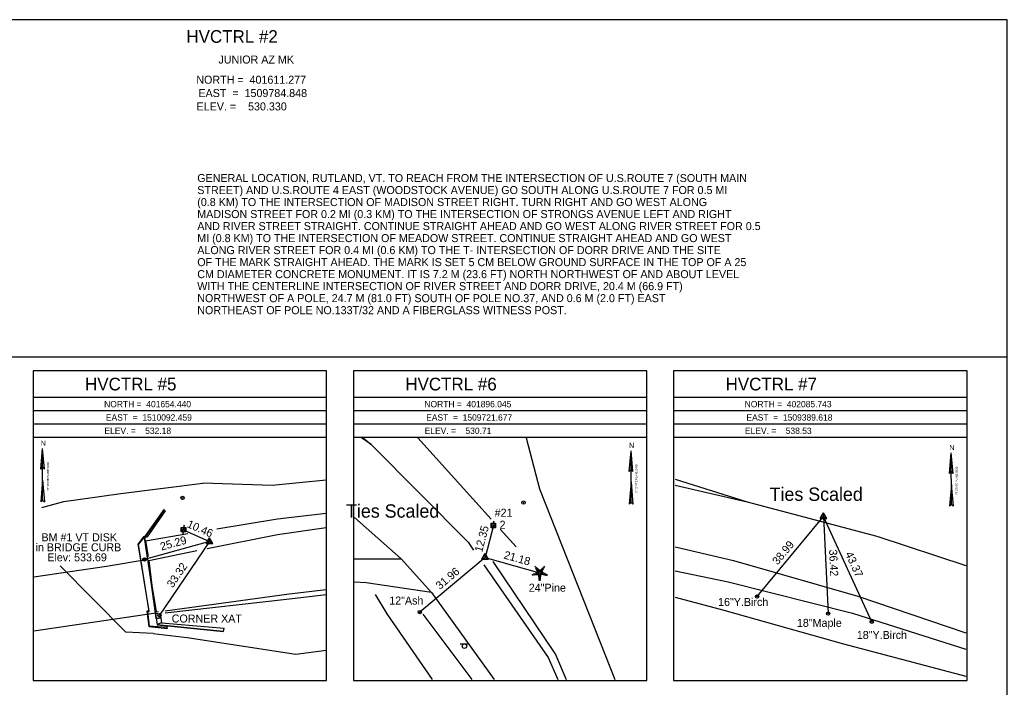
# Model space of a CAD drawing. Extents: x 1508412 to 1509054, y 401108 to 401963.
# Drawn here: x 1508683.7 to 1509053.7, y 401713.1 to 401963.2 of the extents above; entities that cross this region are included whole.
import ezdxf

# ---------------------------------------------------------------- set-up
doc = ezdxf.new("R2010")
doc.units = 0
for name, color, linetype in [('BDC', 7, 'Continuous'), ('BSE', 7, 'Continuous'), ('BSUBM', 7, 'Continuous'), ('C_C', 7, 'Continuous'), ('CBP', 7, 'Continuous'), ('CPBM', 7, 'Continuous'), ('CPSM', 7, 'Continuous'), ('Default', 7, 'Continuous'), ('LAWA', 7, 'Continuous'), ('LAWE', 7, 'Continuous'), ('Level 3', 7, 'Continuous'), ('Level 5', 7, 'Continuous'), ('LTC', 7, 'Continuous'), ('LWS', 7, 'Continuous'), ('NBL2', 7, 'Continuous'), ('NNA_P', 7, 'Continuous'), ('PET', 7, 'Continuous'), ('PSU', 7, 'Continuous'), ('RDP', 7, 'Continuous'), ('RGR', 7, 'Continuous'), ('SSGN', 7, 'Continuous'), ('UP', 7, 'Continuous'), ('UPGW', 7, 'Continuous')]:
    doc.layers.add(name, color=color, linetype=linetype)

msp = doc.modelspace()

# ---------------------------------------------------------------- linework, layer by layer
at = {"layer": 'BDC'}
for points in [[(1508689.03, 401754.45), (1508716.24, 401758.54)], [(1508716.24, 401758.54), (1508731.85, 401761.16)], [(1508689.03, 401734.24), (1508719.4, 401738.76), (1508734.63, 401741.06)]]:
    msp.add_lwpolyline(points, dxfattribs=at)
at = {"layer": 'BSE'}
for points in [[(1508731.54, 401741.47), (1508732.19, 401741.56), (1508728.25, 401766.61), (1508730.36, 401769.29)], [(1508730.36, 401769.29), (1508731.48, 401761.61)], [(1508732.16, 401741.58), (1508728.02, 401766.85)], [(1508731.71, 401760.08), (1508735.14, 401736.56)], [(1508732.16, 401741.58), (1508731.28, 401741.57)], [(1508731.54, 401741.47), (1508732.22, 401736.07)]]:
    msp.add_lwpolyline(points, dxfattribs=at)
at = {"layer": 'BSUBM'}
for points in [[(1508730.56, 401769.42), (1508737.9, 401779.85)], [(1508737.22, 401778.51), (1508730.55, 401769.31)], [(1508731.54, 401769.42), (1508738.27, 401779.16)], [(1508738.27, 401779.16), (1508737.22, 401778.51)], [(1508730.01, 401769.45), (1508728.02, 401766.85)], [(1508730.56, 401769.42), (1508730.01, 401769.45)], [(1508730.81, 401769.29), (1508730.55, 401769.31)], [(1508731.62, 401761.72), (1508730.55, 401769.31)], [(1508731.54, 401769.42), (1508730.81, 401769.29)], [(1508734.55, 401740.84), (1508731.76, 401760.74)], [(1508731.28, 401741.57), (1508732.08, 401735.87), (1508739.02, 401735.15)], [(1508736.31, 401740.6), (1508736.5, 401739.11), (1508734.85, 401738.87), (1508734.55, 401740.84)], [(1508734.55, 401740.84), (1508736.31, 401740.6)], [(1508734.86, 401738.85), (1508736.51, 401739.1), (1508736.81, 401737.22), (1508735.19, 401736.59), (1508759.98, 401733.99)], [(1508738.87, 401735.46), (1508732.22, 401736.07)], [(1508734.86, 401738.85), (1508735.19, 401736.59)], [(1508735.14, 401736.56), (1508738.99, 401736.1)], [(1508736.81, 401737.22), (1508760.25, 401735.2)], [(1508738.87, 401735.46), (1508738.99, 401736.1)], [(1508738.96, 401735.32), (1508739, 401736.08)], [(1508739, 401736.08), (1508759.98, 401733.99)], [(1508759.98, 401733.99), (1508739, 401736.08)], [(1508738.96, 401735.32), (1508739.02, 401735.15)], [(1508759.98, 401733.95), (1508760.25, 401735.2)]]:
    msp.add_lwpolyline(points, dxfattribs=at)
at = {"layer": 'CBP'}
for centre, radius in [((1508745.24, 401771.96), 0.625), ((1508861.19, 401773.72), 0.625), ((1508861.19, 401773.72), 0.0833), ((1508745.24, 401771.96), 0.0833), ((1508730.43, 401761), 0.625), ((1508730.43, 401761), 0.0833), ((1508878.39, 401756.04), 0.625), ((1508878.39, 401756.04), 0.625), ((1508878.39, 401756.04), 0.0833), ((1508878.39, 401756.04), 0.0833), ((1508959.96, 401747.11), 0.625), ((1508959.96, 401747.11), 0.0833), ((1508736.04, 401740.19), 0.625), ((1508736.04, 401740.19), 0.0833), ((1508833.55, 401741.27), 0.625), ((1508833.55, 401741.27), 0.0833), ((1508986.54, 401740.7), 0.625), ((1508986.54, 401740.7), 0.0833), ((1509002.92, 401737.66), 0.625), ((1509002.92, 401737.66), 0.0833)]:
    msp.add_circle(centre, radius, dxfattribs=at)
at = {"layer": 'CPBM'}
for p, q in [((1508729.97, 401760.53), (1508729.97, 401761.53)), ((1508729.97, 401761.53), (1508730.97, 401761.53)), ((1508730.97, 401761.53), (1508730.97, 401760.53)), ((1508730.97, 401760.53), (1508729.97, 401760.53)), ((1508730.47, 401761.03), (1508730.47, 401761.03)), ((1508730.47, 401761.03), (1508730.47, 401761.03))]:
    msp.add_line(p, q, dxfattribs=at)
at = {"layer": 'CPSM'}
for p, q in [((1508983.61, 401776.36), (1508984.86, 401778.53)), ((1508983.61, 401776.36), (1508984.86, 401777.09)), ((1508983.61, 401776.36), (1508986.11, 401776.36)), ((1508986.11, 401776.36), (1508984.86, 401778.53)), ((1508984.86, 401777.09), (1508984.86, 401778.53)), ((1508984.86, 401777.09), (1508984.86, 401777.09)), ((1508984.86, 401777.09), (1508986.11, 401776.36)), ((1508753.56, 401767), (1508754.81, 401769.16)), ((1508756.06, 401767), (1508754.81, 401769.16)), ((1508754.81, 401767.72), (1508754.81, 401769.16)), ((1508753.56, 401767), (1508754.81, 401767.72)), ((1508753.56, 401767), (1508756.06, 401767)), ((1508754.81, 401767.72), (1508754.81, 401767.72)), ((1508754.81, 401767.72), (1508756.06, 401767)), ((1508856.78, 401761.06), (1508858.03, 401763.23)), ((1508856.78, 401761.06), (1508858.03, 401761.78)), ((1508859.28, 401761.06), (1508858.03, 401763.23)), ((1508858.03, 401761.78), (1508858.03, 401763.23)), ((1508858.03, 401761.78), (1508858.03, 401761.78)), ((1508858.03, 401761.78), (1508859.28, 401761.06)), ((1508856.78, 401761.06), (1508859.28, 401761.06))]:
    msp.add_line(p, q, dxfattribs=at)
at = {"layer": 'Default'}
for p, q in [((1508959.96, 401747.11), (1508984.86, 401777.09)), ((1508984.86, 401777.09), (1508986.54, 401740.7)), ((1509002.92, 401737.66), (1508984.86, 401777.09)), ((1508861.19, 401773.72), (1508858.03, 401761.78)), ((1508745.24, 401771.96), (1508754.81, 401767.72)), ((1508754.81, 401767.72), (1508730.43, 401761)), ((1508754.81, 401767.72), (1508736.04, 401740.19)), ((1508858.03, 401761.78), (1508833.55, 401741.27)), ((1508858.03, 401761.78), (1508878.39, 401756.04))]:
    msp.add_line(p, q, dxfattribs=at)
at = {"layer": 'LAWA'}
for points in [[(1508832.82, 401806.62), (1508860.3, 401776.14)], [(1508721.53, 401785.74), (1508752.28, 401789.55)], [(1508778.27, 401788.65), (1508752.28, 401789.55)], [(1508798.48, 401790.65), (1508778.27, 401788.65)], [(1508692.03, 401780.41), (1508700.17, 401782.75), (1508721.53, 401785.74)], [(1508863.72, 401772.34), (1508869.72, 401765.68)], [(1508929.26, 401756.77), (1508949.08, 401752.63), (1508995.7, 401740.87), (1509038.18, 401727.36)], [(1508834.78, 401740.47), (1508853.11, 401716.01)]]:
    msp.add_lwpolyline(points, dxfattribs=at)
at = {"layer": 'LAWE'}
for points in [[(1508873.43, 401806.62), (1508878.48, 401787.48), (1508903.11, 401724.88), (1508906.66, 401716.01)], [(1508723.5, 401733.76), (1508698.84, 401758.59)], [(1508733.69, 401733.3), (1508723.5, 401733.76)], [(1508733.69, 401733.3), (1508746.39, 401731.75), (1508787.1, 401725.55), (1508798.48, 401727.05)]]:
    msp.add_lwpolyline(points, dxfattribs=at)
at = {"layer": 'LTC'}
for p, q in [((1508876.64, 401758.21), (1508877, 401758.47)), ((1508876.85, 401757.75), (1508877.38, 401758.13)), ((1508877.06, 401757.28), (1508877.77, 401757.79)), ((1508879.3, 401757.76), (1508879.98, 401757.26)), ((1508879.67, 401758.1), (1508880.22, 401757.71)), ((1508880.04, 401758.45), (1508880.46, 401758.15)), ((1508875.68, 401755.49), (1508875.83, 401755.02)), ((1508876.13, 401755.71), (1508876.34, 401755.06)), ((1508876.59, 401755.92), (1508876.86, 401755.09)), ((1508877.04, 401756.14), (1508877.37, 401755.12)), ((1508877.27, 401756.82), (1508878.15, 401757.45)), ((1508877.5, 401756.36), (1508878.51, 401757.09)), ((1508877.5, 401756.36), (1508877.88, 401755.17)), ((1508879.11, 401755.17), (1508877.88, 401755.17)), ((1508879.08, 401754.67), (1508877.93, 401754.67)), ((1508878.99, 401754.17), (1508878, 401754.17)), ((1508878.51, 401757.09), (1508879.51, 401756.37)), ((1508878.93, 401757.41), (1508879.74, 401756.82)), ((1508879.51, 401756.37), (1508879.11, 401755.17)), ((1508879.94, 401756.1), (1508879.61, 401755.06)), ((1508880.39, 401755.85), (1508880.1, 401754.96)), ((1508880.83, 401755.6), (1508880.6, 401754.87)), ((1508881.28, 401755.35), (1508881.09, 401754.77)), ((1508878.91, 401753.67), (1508878.08, 401753.67)), ((1508878.83, 401753.17), (1508878.15, 401753.17))]:
    msp.add_line(p, q, dxfattribs=at)
at = {"layer": 'LWS'}
for points in [[(1508816.81, 401747.83), (1508821.29, 401740.62), (1508838.21, 401716.01)], [(1508929.26, 401746.9), (1508947.52, 401742.01), (1508992.29, 401729.33), (1509038.18, 401717.22)]]:
    msp.add_lwpolyline(points, dxfattribs=at)
at = {"layer": 'NBL2'}
for p, q in [((1508413.7, 401836.87), (1509053.7, 401836.87)), ((1508798.69, 401821.71), (1508688.69, 401821.71)), ((1508918.69, 401821.71), (1508808.69, 401821.71)), ((1509038.69, 401821.71), (1508928.69, 401821.71)), ((1508798.69, 401816.71), (1508688.69, 401816.71)), ((1508918.69, 401816.71), (1508808.69, 401816.71)), ((1509038.69, 401816.71), (1508928.69, 401816.71)), ((1508798.69, 401811.71), (1508688.69, 401811.71)), ((1508918.69, 401811.71), (1508808.69, 401811.71)), ((1509038.69, 401811.71), (1508928.69, 401811.71)), ((1508798.69, 401806.71), (1508688.69, 401806.71)), ((1508918.69, 401806.71), (1508808.69, 401806.71)), ((1509038.69, 401806.71), (1508928.69, 401806.71))]:
    msp.add_line(p, q, dxfattribs=at)
for points in [[(1508413.7, 401543.21), (1509053.7, 401543.21), (1509053.7, 401963.21), (1508413.7, 401963.21)], [(1508688.69, 401715.71), (1508798.69, 401715.71), (1508798.69, 401831.71), (1508688.69, 401831.71)], [(1508808.69, 401715.71), (1508918.69, 401715.71), (1508918.69, 401831.71), (1508808.69, 401831.71)], [(1508928.69, 401715.71), (1509038.69, 401715.71), (1509038.69, 401831.71), (1508928.69, 401831.71)]]:
    msp.add_lwpolyline(points, close=True, dxfattribs=at)
at = {"layer": 'NNA_P'}
for p, q in [((1508691.56, 401794.8), (1508692.26, 401802.59)), ((1508692.26, 401783.22), (1508692.26, 401802.59)), ((1508692.95, 401794.8), (1508692.26, 401802.59)), ((1508912.04, 401793.97), (1508912.73, 401801.76)), ((1508912.74, 401782.39), (1508912.73, 401801.76)), ((1508913.43, 401793.97), (1508912.73, 401801.76)), ((1509032.05, 401793.15), (1509032.74, 401800.94)), ((1509032.75, 401781.56), (1509032.74, 401800.94)), ((1509033.44, 401793.15), (1509032.74, 401800.94)), ((1508691.56, 401794.8), (1508692.26, 401795.56)), ((1508692.95, 401794.8), (1508692.26, 401795.56)), ((1508912.04, 401793.97), (1508912.73, 401794.74)), ((1508913.43, 401793.97), (1508912.74, 401794.74)), ((1509032.05, 401793.15), (1509032.74, 401793.91)), ((1509033.44, 401793.15), (1509032.75, 401793.91)), ((1508692.26, 401790.74), (1508691.54, 401782.58)), ((1508692.26, 401790.74), (1508692.98, 401782.58)), ((1508912.74, 401789.91), (1508912.02, 401781.75)), ((1508912.74, 401789.91), (1508913.46, 401781.75)), ((1509032.75, 401789.09), (1509032.03, 401780.92)), ((1509032.74, 401789.09), (1509033.47, 401780.92)), ((1508692.26, 401783.21), (1508691.54, 401782.58)), ((1508692.26, 401783.21), (1508692.98, 401782.58)), ((1508912.74, 401782.39), (1508912.02, 401781.75)), ((1508912.74, 401782.39), (1508913.46, 401781.75)), ((1509032.75, 401781.56), (1509032.03, 401780.92)), ((1509032.75, 401781.56), (1509033.47, 401780.92))]:
    msp.add_line(p, q, dxfattribs=at)
at = {"layer": 'PET'}
for points in [[(1508815.35, 401804.11), (1508811.71, 401806.62)], [(1508851.67, 401767.46), (1508815.35, 401804.11)], [(1508929.26, 401788.78), (1508956.25, 401782.64), (1509004.84, 401769.69), (1509038.18, 401758.68)], [(1508826.63, 401761.2), (1508809.11, 401776.67)], [(1508753.96, 401765.09), (1508780.3, 401770.4), (1508798.48, 401772.95)], [(1508730.87, 401768.03), (1508731.83, 401762.08)], [(1508851.67, 401767.46), (1508853.76, 401764.46)], [(1508929.26, 401765.67), (1508951.17, 401760.64), (1508997.71, 401747.22), (1509038.18, 401733.55)], [(1508732.06, 401760.66), (1508750.08, 401764.3)], [(1508732.06, 401760.66), (1508733.17, 401751.23), (1508734.76, 401741.32), (1508735.7, 401741.45)], [(1508826.63, 401761.2), (1508838, 401748.61), (1508861.41, 401716.01)], [(1508857.55, 401759), (1508881.68, 401724.26), (1508885.33, 401716.01)], [(1508738.16, 401741.78), (1508784.66, 401748.09), (1508798.48, 401749.78)]]:
    msp.add_lwpolyline(points, dxfattribs=at)
at = {"layer": 'PSU'}
for points in [[(1508812.35, 401806.62), (1508815.35, 401804.11)], [(1508929.26, 401791.1), (1508956.25, 401782.64)]]:
    msp.add_lwpolyline(points, dxfattribs=at)
at = {"layer": 'RDP'}
for points in [[(1508809.11, 401761.21), (1508826.63, 401761.2)], [(1508838, 401748.61), (1508813.52, 401752.26), (1508809.11, 401752.47)]]:
    msp.add_lwpolyline(points, dxfattribs=at)
at = {"layer": 'RGR'}
for points in [[(1508757.54, 401772.49), (1508780.24, 401776.28), (1508798.48, 401778.31)], [(1508730.87, 401768.03), (1508746.73, 401770.68)], [(1508860.99, 401760.2), (1508884.4, 401725.39), (1508888.42, 401716.01)], [(1508738.23, 401741), (1508784.81, 401746.26), (1508798.48, 401747.89)]]:
    msp.add_lwpolyline(points, dxfattribs=at)
at = {"layer": 'SSGN'}
for p, q in [((1508848.67, 401729.33), (1508852, 401729.33)), ((1508850.32, 401728.5), (1508850.32, 401728.5))]:
    msp.add_line(p, q, dxfattribs=at)
msp.add_circle((1508850.32, 401728.5), 0.833, dxfattribs=at)
at = {"layer": 'UP'}
for p, q in [((1508744.21, 401771.32), (1508744.21, 401772.98)), ((1508744.21, 401772.98), (1508745.88, 401772.98)), ((1508745.3, 401773.82), (1508745.05, 401772.98)), ((1508745.88, 401772.98), (1508745.88, 401771.32)), ((1508860.27, 401772.89), (1508860.27, 401774.56)), ((1508860.27, 401774.56), (1508861.94, 401774.56)), ((1508861.94, 401772.89), (1508860.27, 401772.89)), ((1508860.85, 401772.06), (1508861.1, 401772.89)), ((1508861.35, 401775.39), (1508861.1, 401774.56)), ((1508861.1, 401773.73), (1508861.1, 401773.73)), ((1508861.94, 401774.56), (1508861.94, 401772.89)), ((1508745.88, 401771.32), (1508744.21, 401771.32)), ((1508744.8, 401770.48), (1508745.05, 401771.32)), ((1508745.05, 401772.15), (1508745.05, 401772.15))]:
    msp.add_line(p, q, dxfattribs=at)
for centre in [(1508745.05, 401772.15), (1508861.1, 401773.73)]:
    msp.add_circle(centre, 0.833, dxfattribs=at)
at = {"layer": 'UPGW'}
for centre, radius in [((1508744.71, 401784.04), 0.625), ((1508744.71, 401784.04), 0.0833), ((1508872.44, 401782.29), 0.625), ((1508872.44, 401782.29), 0.0833)]:
    msp.add_circle(centre, radius, dxfattribs=at)

# ---------------------------------------------------------------- texts
at = {"layer": 'C_C'}
for s, p in [('BM #1 VT DISK', (1508691.83, 401767.81)), ('in BRIDGE CURB', (1508689.63, 401764.06)), ('Elev: 533.69', (1508694.02, 401760.3)), ('CORNER XAT', (1508740.63, 401737.35))]:
    msp.add_text(s, height=3, dxfattribs=at).set_placement(p)
at = {"layer": 'Default'}
for s, p in [('GENERAL LOCATION, RUTLAND, VT. TO REACH FROM THE INTERSECTION OF U.S.ROUTE 7 (SOUTH MAIN ', (1508750.21, 401902.4)), ('STREET) AND U.S.ROUTE 4 EAST (WOODSTOCK AVENUE) GO SOUTH ALONG U.S.ROUTE 7 FOR 0.5 MI ', (1508750.21, 401897.9)), ('(0.8 KM) TO THE INTERSECTION OF MADISON STREET RIGHT. TURN RIGHT AND GO WEST ALONG ', (1508750.21, 401893.4)), ('MADISON STREET FOR 0.2 MI (0.3 KM) TO THE INTERSECTION OF STRONGS AVENUE LEFT AND RIGHT ', (1508750.21, 401888.9)), ('AND RIVER STREET STRAIGHT. CONTINUE STRAIGHT AHEAD AND GO WEST ALONG RIVER STREET FOR 0.5 ', (1508750.21, 401884.4)), ('MI (0.8 KM) TO THE INTERSECTION OF MEADOW STREET. CONTINUE STRAIGHT AHEAD AND GO WEST ', (1508750.21, 401879.9)), ('ALONG RIVER STREET FOR 0.4 MI (0.6 KM) TO THE T- INTERSECTION OF DORR DRIVE AND THE SITE ', (1508750.21, 401875.4)), ('OF THE MARK STRAIGHT AHEAD. THE MARK IS SET 5 CM BELOW GROUND SURFACE IN THE TOP OF A 25 ', (1508750.21, 401870.9)), ('CM DIAMETER CONCRETE MONUMENT. IT IS 7.2 M (23.6 FT) NORTH NORTHWEST OF AND ABOUT LEVEL ', (1508750.21, 401866.4)), ('WITH THE CENTERLINE INTERSECTION OF RIVER STREET AND DORR DRIVE, 20.4 M (66.9 FT) ', (1508750.21, 401861.9)), ('NORTHWEST OF A POLE, 24.7 M (81.0 FT) SOUTH OF POLE NO.37, AND 0.6 M (2.0 FT) EAST ', (1508750.21, 401857.4)), ('NORTHEAST OF POLE NO.133T/32 AND A FIBERGLASS WITNESS POST.', (1508750.21, 401852.9))]:
    msp.add_text(s, height=3, dxfattribs=at).set_placement(p)
at = {"layer": 'Level 3'}
for s, p in [('#21', (1508861.63, 401777.01)), ('2', (1508863.47, 401772.51)), ('24"Pine', (1508874.41, 401748.92)), ('12"Ash', (1508822.14, 401744.11)), ('16"Y.Birch', (1508945.35, 401743.57)), ('18"Maple', (1508974.88, 401735.74)), ('18"Y.Birch', (1508997.33, 401731.21))]:
    msp.add_text(s, height=3, dxfattribs=at).set_placement(p)
for s, rotation, p in [('10.46', 336.111, (1508746.09, 401773.22)), ('12.35', 75.1971, (1508856.94, 401763.52)), ('25.29', 15.4057, (1508736.79, 401764.31)), ('38.99', 50.2853, (1508967.66, 401758.72)), ('21.18', 344.2381, (1508864.84, 401761.42)), ('36.42', 272.6485, (1508986.94, 401764.65)), ('43.37', 294.6165, (1508992.91, 401763.11)), ('33.32', 55.7046, (1508741.02, 401750.16)), ('31.96', 39.9571, (1508841.11, 401749.56))]:
    msp.add_text(s, height=3, rotation=rotation, dxfattribs=at).set_placement(p)
at = {"layer": 'Level 5'}
for p in [(1508964.64, 401782.95), (1508805.94, 401776.65)]:
    msp.add_text('Ties Scaled', height=5, dxfattribs=at).set_placement(p)
at = {"layer": 'LTC'}
msp.add_text('.', height=1.04, rotation=270, dxfattribs=at).set_placement((1508878.39, 401756.11))
at = {"layer": 'NBL2'}
for s, height, p in [('     HVCTRL #2     ', 4.75, (1508737.31, 401954.56)), ('JUNIOR AZ MK', 3, (1508758.15, 401946.8)), ('NORTH =  401611.277 ', 3, (1508749.85, 401939.24)), ('EAST  =  1509784.848', 3, (1508750.64, 401934.24)), ('ELEV. =    530.330  ', 3, (1508749.95, 401929.24)), ('     HVCTRL #5     ', 4.75, (1508699.34, 401824.33)), ('     HVCTRL #6     ', 4.75, (1508819.34, 401824.33)), ('     HVCTRL #7     ', 4.75, (1508939.34, 401824.33)), ('NORTH =  401654.440 ', 2.375, (1508715.31, 401818.02)), ('NORTH =  401896.045 ', 2.375, (1508835.31, 401818.02)), ('NORTH =  402085.743 ', 2.375, (1508955.31, 401818.02)), ('EAST  =  1510092.459', 2.375, (1508715.96, 401813.02)), ('EAST  =  1509721.677', 2.375, (1508835.97, 401813.02)), ('EAST  =  1509389.618', 2.375, (1508955.97, 401813.02)), ('ELEV. =    532.18   ', 2.375, (1508715.42, 401808.02)), ('ELEV. =    530.71   ', 2.375, (1508835.42, 401808.02)), ('ELEV. =    538.53   ', 2.375, (1508955.42, 401808.02))]:
    msp.add_text(s, height=height, dxfattribs=at).set_placement(p)
at = {"layer": 'NNA_P'}
for p in [(1508691.5, 401803.6), (1508911.97, 401802.77), (1509031.98, 401801.95)]:
    msp.add_text('N', height=1.97, dxfattribs=at).set_placement(p)
for p in [(1508694.61, 401786.78), (1508915.09, 401785.95), (1509035.1, 401785.13)]:
    msp.add_text('VT STATE PLANE GRID', height=0.7, rotation=90.0204, dxfattribs=at).set_placement(p)

doc.saveas('drawing.dxf')
